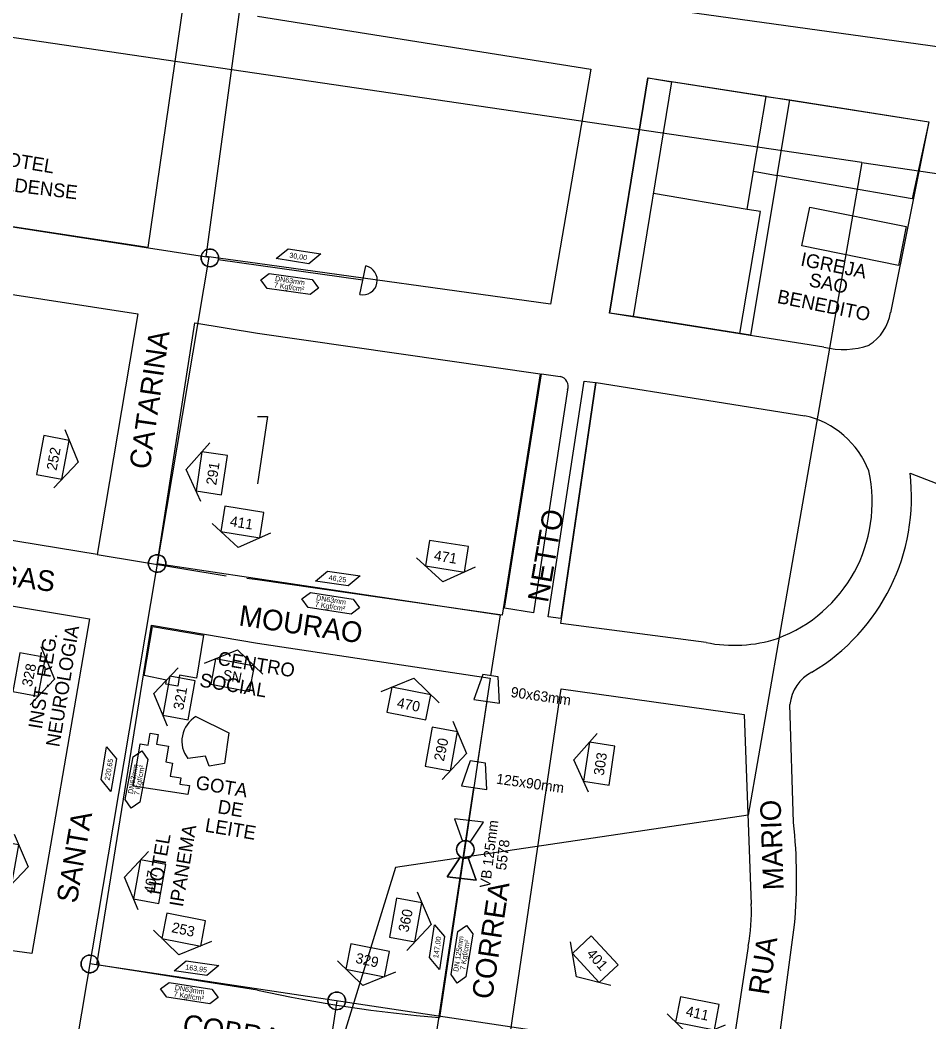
# Model space of a CAD drawing. Extents: x 325709 to 364434, y 7573432 to 7597073.
# Drawn here: x 338412.3 to 338676.7, y 7589659.1 to 7589950.5 of the extents above; entities that cross this region are included whole.
import ezdxf

# ---------------------------------------------------------------- set-up
doc = ezdxf.new("R2010")
doc.units = 0
for name, color, linetype in [('EDIFEXISTENT', 7, 'Continuous'), ('EDIFIDENTIF', 7, 'Continuous'), ('EDIFOBRAEXIS', 7, 'Continuous'), ('FORMATO', 7, 'Continuous'), ('LIMITE_BAIRROS_MUNICIPIOS', 7, 'Continuous'), ('LOGRADOURO', 7, 'Continuous'), ('LOGRADOURO_TEXTO', 7, 'Continuous'), ('NUM_REF', 7, 'Continuous'), ('SIMBOLO', 7, 'Continuous'), ('TEXTO', 7, 'Continuous'), ('TUBO_PEAD_GN_125', 7, 'Continuous'), ('TUBO_PEAD_GN_63', 7, 'Continuous'), ('TUBO_PEAD_GN_90', 7, 'Continuous'), ('VALVULA_PEAD_125', 7, 'Continuous')]:
    doc.layers.add(name, color=color, linetype=linetype)

# ---------------------------------------------------------------- blocks, each defined once
blk = doc.blocks.new('INTERLIGACAO')
at = {"layer": 'SIMBOLO'}
blk.add_circle((0, 0), 1.28, dxfattribs=at)
for start, end in [(0, 180), (180, 0)]:
    blk.add_arc((0, 0), 1.28, start, end, dxfattribs=at)
blk = doc.blocks.new('VALVULA_PEAD_DN_125')
at = {"layer": 'VALVULA_PEAD_125'}
for points in [[(-1.14, 0.57), (-4.25, 2.13), (-4.25, -2.13), (-1.14, -0.57)], [(-1.14, -0.57), (-4.25, -2.13), (-4.25, 2.13), (-1.14, 0.57)], [(1.14, -0.57), (4.25, -2.13), (4.25, 2.13), (1.14, 0.57)], [(1.14, -0.57), (4.25, -2.13), (4.25, 2.13), (1.14, 0.57)]]:
    blk.add_lwpolyline(points, dxfattribs=at)
blk.add_circle((0, 0), 1.28, dxfattribs=at)
for start, end in [(90, 270), (153.4349, 206.5651), (270, 90), (0, 26.5651), (333.4349, 0)]:
    blk.add_arc((0, 0), 1.28, start, end, dxfattribs=at)
blk = doc.blocks.new('NUM_REF')
at = {"layer": 'NUM_REF'}
blk.add_lwpolyline([(-4.3125, 0.9375), (0, 3.75), (4.3125, 0.9375)], dxfattribs=at)
blk.add_lwpolyline([(2.875, -1.875), (2.875, 1.875), (-2.875, 1.875), (-2.875, -1.875)], close=True, dxfattribs=at)

msp = doc.modelspace()

# ---------------------------------------------------------------- linework, layer by layer
at = {"layer": 'EDIFEXISTENT'}
for p, q in [((338639.76, 7589884.83), (338642.03, 7589896.12)), ((338642.03, 7589896.12), (338670.08, 7589890.5)), ((338670.08, 7589890.5), (338667.8, 7589879.14)), ((338667.8, 7589879.14), (338639.76, 7589884.83)), ((338448.43, 7589759.9), (338450.8, 7589774.11)), ((338450.8, 7589774.11), (338465.71, 7589771.65)), ((338465.71, 7589771.65), (338463.62, 7589759.14)), ((338454.92, 7589758.53), (338448.43, 7589759.9)), ((338454.73, 7589757.35), (338454.92, 7589758.53)), ((338458.72, 7589759.95), (338458.19, 7589756.77)), ((338463.62, 7589759.14), (338458.72, 7589759.95)), ((338458.19, 7589756.77), (338454.73, 7589757.35)), ((338463.45, 7589747.92), (338473.02, 7589743.23)), ((338449.53, 7589739.59), (338450.12, 7589743.11)), ((338450.12, 7589743.11), (338452.5, 7589742.71)), ((338473.02, 7589743.23), (338471.76, 7589734.27)), ((338452.5, 7589742.71), (338452.02, 7589739.86)), ((338445.21, 7589727.73), (338447.24, 7589739.97)), ((338447.24, 7589739.97), (338449.53, 7589739.59)), ((338452.02, 7589739.86), (338455.45, 7589739.28)), ((338455.45, 7589739.28), (338454.69, 7589734.73)), ((338454.69, 7589734.73), (338456.63, 7589734.4)), ((338456.63, 7589734.4), (338456, 7589730.59)), ((338466.26, 7589736.44), (338461.1, 7589735.74)), ((338467.36, 7589733.47), (338466.26, 7589736.44)), ((338471.76, 7589734.27), (338467.36, 7589733.47)), ((338456, 7589730.59), (338459.11, 7589730.07)), ((338459.11, 7589730.07), (338458.81, 7589728.31)), ((338461.12, 7589725.27), (338445.21, 7589727.73)), ((338458.81, 7589728.31), (338461.55, 7589727.85)), ((338461.55, 7589727.85), (338461.12, 7589725.27))]:
    msp.add_line(p, q, dxfattribs=at)
msp.add_arc((338467.66, 7589740.79), 8.28, 120.5749, 217.6076, dxfattribs=at)
at = {"layer": 'EDIFOBRAEXIS'}
for p, q in [((338629.36, 7589928.3), (338601.76, 7589932.58)), ((338623.84, 7589895.45), (338596.59, 7589900.03)), ((338553.2, 7589779.46), (338563.95, 7589847.61)), ((338563.95, 7589847.61), (338569.45, 7589846.88))]:
    msp.add_line(p, q, dxfattribs=at)
for points in [[(338595.05, 7589933.71), (338601.76, 7589932.58), (338590.63, 7589864.25), (338583.85, 7589865.24), (338595.05, 7589933.71)], [(338632.55, 7589905.28), (338636.26, 7589927.32), (338676.66, 7589920.95), (338671.85, 7589898.5), (338632.55, 7589905.28), (338624.74, 7589858.83), (338590.63, 7589864.25)], [(338625.7, 7589906.53), (338629.36, 7589928.3), (338636.26, 7589927.32)], [(338621.68, 7589859.31), (338627.65, 7589894.8), (338623.84, 7589895.45), (338625.7, 7589906.53), (338632.55, 7589905.28)], [(338576.43, 7589845.49), (338579.7, 7589845.06), (338569.6, 7589776.44), (338565.96, 7589776.96), (338576.43, 7589845.49)], [(338571.58, 7589842.92), (338561.71, 7589778.11), (338553.2, 7589779.46)], [(338481.39, 7589835.2), (338484.25, 7589835.24), (338481.39, 7589815.66)]]:
    msp.add_lwpolyline(points, dxfattribs=at)
msp.add_arc((338568.75, 7589843.95), 3.01, 340.1239, 76.6385, dxfattribs=at)
at = {"layer": 'LIMITE_BAIRROS_MUNICIPIOS'}
for points in [[(338657.19, 7589909.08), (338356.45, 7589953.26), (338434.11, 7590441.43), (338663.22, 7590410.21), (338845.4, 7590916.1), (338997.9, 7590425.8), (339063.34, 7590450), (338912.59, 7589871.56)], [(338657.19, 7589909.08), (338624.06, 7589719.21), (338521.53, 7589704.01), (338334.9, 7589099.85)], [(338657.19, 7589909.08), (338912.59, 7589871.56), (338870.82, 7589718.61), (338775.61, 7589646.81), (338916.66, 7589627.18)]]:
    msp.add_lwpolyline(points, dxfattribs=at)
at = {"layer": 'LOGRADOURO'}
for p, q in [((338459.81, 7589955.81), (338449.46, 7589884.34)), ((338702.07, 7589939.52), (338599.37, 7589953.79)), ((338466.44, 7589881.7), (338476.15, 7589952.8)), ((338481.39, 7589951.68), (338578.31, 7589936.19)), ((338578.31, 7589936.19), (338566.58, 7589867.92)), ((338583.75, 7589865.24), (338594.94, 7589933.71)), ((338594.94, 7589933.71), (338676.66, 7589920.95)), ((338676.66, 7589920.95), (338665.53, 7589865.4)), ((338449.46, 7589884.34), (338347.7, 7589899.92)), ((338344.5, 7589880.7), (338446.57, 7589865.1)), ((338481.39, 7589879.69), (338466.44, 7589881.7)), ((338566.58, 7589867.92), (338481.39, 7589879.69)), ((338446.57, 7589865.1), (338434.76, 7589795.04)), ((338646.16, 7589855.4), (338583.75, 7589865.24)), ((338452.15, 7589792.12), (338463.14, 7589862.44)), ((338463.14, 7589862.44), (338481.39, 7589859.4)), ((338481.39, 7589859.4), (338563.59, 7589847.61)), ((338563.59, 7589847.61), (338552.52, 7589777.4)), ((338569.59, 7589775.02), (338579.88, 7589845.11)), ((338579.88, 7589845.11), (338640.62, 7589835.42)), ((338671.22, 7589818.75), (338679.02, 7589815.75)), ((338434.76, 7589795.04), (338332.86, 7589811.81)), ((338330.98, 7589793.1), (338432.47, 7589776.35)), ((338472.25, 7589788.79), (338434.77, 7589795)), ((338481.39, 7589787.68), (338478.26, 7589788.06)), ((338552.52, 7589777.4), (338481.39, 7589787.68)), ((338432.47, 7589776.35), (338415.76, 7589678.98)), ((338434.61, 7589675.68), (338450.52, 7589774.49)), ((338450.52, 7589774.49), (338481.39, 7589769.31)), ((338611.85, 7589769.48), (338569.59, 7589775.02)), ((338481.39, 7589769.31), (338549.08, 7589759.07)), ((338549.08, 7589759.07), (338534.31, 7589660.36)), ((338555.1, 7589656.84), (338569.67, 7589755.95)), ((338569.67, 7589755.95), (338622.97, 7589748.52)), ((338637.32, 7589717.1), (338636.25, 7589751.42)), ((338622.97, 7589748.52), (338625.01, 7589693.41)), ((338415.76, 7589678.98), (338368.65, 7589685.54)), ((338632.15, 7589646.32), (338637.59, 7589687.34)), ((338624.08, 7589681.1), (338619.44, 7589650.41)), ((338481.39, 7589668.37), (338434.61, 7589675.68))]:
    msp.add_line(p, q, dxfattribs=at)
for centre, radius, start, end in [((338651.76, 7589867.74), 13.96, 302.7485, 350.3695), ((338651.76, 7589877.02), 22.34, 255.4876, 289.7614), ((338634.73, 7589809.83), 26.26, 21.2953, 77.0253), ((338617.95, 7589810.26), 42.23, 290.2865, 12.4538), ((338612.3, 7589811.81), 59.32, 300.7532, 6.7095), ((338620, 7589809.52), 40.87, 258.4936, 287.9446), ((338648, 7589750.32), 11.8, 116.9963, 174.6442), ((338487.33, 7589700.86), 150.87, 354.8597, 6.1799), ((338572.07, 7589691.21), 52.99, 349.0101, 2.3865), ((338569.82, 7590074.08), 415.24, 257.7038, 265.0934)]:
    msp.add_arc(centre, radius, start, end, dxfattribs=at)
at = {"layer": 'SIMBOLO'}
for points in [[(338496.31, 7589879.62), (338486.82, 7589881.11), (338490.3, 7589883.98), (338499.8, 7589882.49)], [(338484.8, 7589876.8), (338497.3, 7589875.03), (338499.16, 7589872.56), (338499.16, 7589872.56), (338496.69, 7589870.7), (338484.19, 7589872.46), (338482.33, 7589874.94), (338482.33, 7589874.94)], [(338507.78, 7589785.95), (338498.26, 7589787.3), (338501.71, 7589790.22), (338511.22, 7589788.87)], [(338496.78, 7589783.98), (338509.25, 7589782.05), (338511.08, 7589779.55), (338511.08, 7589779.55), (338508.58, 7589777.72), (338496.11, 7589779.66), (338494.28, 7589782.16), (338494.28, 7589782.16)], [(338551.78, 7589751.86), (338551.35, 7589759.5), (338546.89, 7589760.13), (338544.35, 7589752.92)], [(338440.32, 7589735.59), (338438.71, 7589726.12), (338435.89, 7589729.64), (338437.49, 7589739.11)], [(338442.86, 7589723.83), (338445.17, 7589736.25), (338447.72, 7589738), (338447.72, 7589738), (338449.47, 7589735.45), (338447.16, 7589723.03), (338444.61, 7589721.28), (338444.61, 7589721.28)], [(338548.11, 7589726.75), (338547.67, 7589734.38), (338543.22, 7589735.01), (338540.68, 7589727.8)], [(338535.74, 7589683.92), (338534.36, 7589674.41), (338531.45, 7589677.86), (338532.83, 7589687.37)], [(338537.68, 7589672.92), (338539.65, 7589685.39), (338542.15, 7589687.21), (338542.15, 7589687.21), (338543.97, 7589684.71), (338542, 7589672.24), (338539.5, 7589670.42), (338539.5, 7589670.42)], [(338466.66, 7589672.58), (338457.15, 7589673.93), (338460.59, 7589676.85), (338470.11, 7589675.5)], [(338455.66, 7589670.61), (338468.14, 7589668.67), (338469.96, 7589666.18), (338469.96, 7589666.18), (338467.47, 7589664.35), (338454.99, 7589666.28), (338453.17, 7589668.78), (338453.17, 7589668.78)]]:
    msp.add_lwpolyline(points, close=True, dxfattribs=at)
at = {"layer": 'TUBO_PEAD_GN_125'}
msp.add_line((338544.24, 7589727.3), (338517.75, 7589553.63), dxfattribs=at)
at = {"layer": 'TUBO_PEAD_GN_63'}
for p, q in [((338342.16, 7589900.77), (338467.18, 7589881.59)), ((338467.18, 7589881.59), (338421.99, 7589612.77)), ((338511.97, 7589874.82), (338469.96, 7589880.81)), ((338512.84, 7589878.98), (338511.09, 7589870.65)), ((338452.19, 7589792.4), (338551.92, 7589777.49)), ((338551.93, 7589777.5), (338549.12, 7589759.82)), ((338631.24, 7589646.28), (338432.62, 7589675.98)), ((338504.43, 7589665.24), (338499.9, 7589635.59))]:
    msp.add_line(p, q, dxfattribs=at)
msp.add_arc((338511.97, 7589874.82), 4.25, 258.156, 78.156, dxfattribs=at)
at = {"layer": 'TUBO_PEAD_GN_90'}
msp.add_line((338548.07, 7589752.39), (338545.37, 7589734.71), dxfattribs=at)

# ---------------------------------------------------------------- block references
at = {"layer": 'FORMATO'}
for p, xscale, yscale, rotation in [((338421.86, 7589823.31), 1.9999999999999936, 1.9999999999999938, -100.70632208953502), ((338468.06, 7589818.7), 1.9999999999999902, 1.9999999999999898, 81.3795703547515), ((338476.98, 7589804.53), 1.9999999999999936, 1.999999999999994, 170.91654670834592), ((338536.48, 7589794.55), 1.9999999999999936, 1.999999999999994, 170.91654670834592), ((338414.95, 7589760.17), 1.9999999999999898, 1.9999999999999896, -100.3090999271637), ((338474.12, 7589759.98), 1.9999999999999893, 1.9999999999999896, -10.741198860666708), ((338458.57, 7589753.32), 1.9999999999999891, 1.9999999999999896, 79.77047945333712), ((338525.41, 7589751.73), 1.9999999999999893, 1.9999999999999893, -11.202265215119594), ((338534.82, 7589738.49), 1.9999999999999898, 1.9999999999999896, -100.3090999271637), ((338580.78, 7589734.22), 1.9999999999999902, 1.9999999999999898, 81.3795703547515), ((338407.24, 7589705.59), 1.9999999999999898, 1.9999999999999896, -100.3090999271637), ((338450.03, 7589699.9), 1.9999999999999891, 1.9999999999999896, 79.77047945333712), ((338524.47, 7589688.76), 1.9999999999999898, 1.9999999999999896, -100.3090999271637), ((338459.92, 7589685.98), 1.9999999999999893, 1.9999999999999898, 168.96254512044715), ((338579.64, 7589677.35), 1.9999999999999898, 1.9999999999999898, 132.7983526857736), ((338513.43, 7589677.06), 1.9999999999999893, 1.9999999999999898, 168.96254512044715), ((338609.34, 7589661.64), 1.9999999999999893, 1.9999999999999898, 168.96254512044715)]:
    msp.add_blockref('NUM_REF', p, dxfattribs=dict(at, xscale=xscale, yscale=yscale, rotation=rotation))
at = {"layer": 'SIMBOLO'}
for p, xscale, yscale, rotation in [((338467.52, 7589881.33), 2, 2, -8.011999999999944), ((338452.18, 7589792.44), 2.0000000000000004, 1.9999999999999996, 22.031790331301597), ((338432.62, 7589675.98), 2.0000000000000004, 1.9999999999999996, 22.031790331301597), ((338504.43, 7589665.24), 2.0000000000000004, 1.9999999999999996, 22.031790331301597)]:
    msp.add_blockref('INTERLIGACAO', p, dxfattribs=dict(at, xscale=xscale, yscale=yscale, rotation=rotation))
at = {"layer": 'VALVULA_PEAD_125', "xscale": 1.9999999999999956, "yscale": 1.9999999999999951, "rotation": 82.88228201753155}
msp.add_blockref('VALVULA_PEAD_DN_125', (338541.84, 7589709.27), dxfattribs=at)

# ---------------------------------------------------------------- texts
for s, rotation, p in [('252', 79.2937, (338422.9, 7589819.35)), ('291', 81.3796, (338469.36, 7589815.08)), ('411', 350.9165, (338473.21, 7589803.35)), ('471', 350.9165, (338532.55, 7589793.4)), ('328', 78.2244, (338415.71, 7589756.44)), ('SN', 349.2588, (338471.04, 7589758.7)), ('321', 79.7705, (338459.78, 7589749.67)), ('470', 348.7977, (338521.75, 7589750.58)), ('290', 78.2244, (338535.58, 7589734.76)), ('303', 81.3796, (338582.08, 7589730.61)), ('VB 125mm', 82.8823, (338548.99, 7589697.93)), ('5578', 82.8823, (338553.66, 7589703.1)), ('407', 79.7705, (338451.23, 7589696.25)), ('360', 78.2244, (338525.22, 7589685.03)), ('253', 347.496, (338456.19, 7589685.27)), ('329', 347.496, (338509.69, 7589676.35)), ('401', 311.3318, (338576.88, 7589678.8)), ('411', 347.496, (338605.76, 7589660.9))]:
    msp.add_text(s, height=3, rotation=rotation).set_placement(p)
at = {"layer": 'EDIFIDENTIF'}
for s, rotation, p in [('HOTEL', 350.6301, (338404.32, 7589908.78)), ('CALDENSE', 353.1046, (338400.16, 7589901.81)), ('IGREJA', 348.67, (338639.14, 7589879.1)), ('SAO', 348.67, (338641.57, 7589873.11)), ('BENEDITO', 348.67, (338632.33, 7589868.26)), ('NEUROLOGIA', 80.6301, (338423.73, 7589738.89)), ('INST. REG.', 80.6301, (338418.62, 7589744.11)), ('CENTRO', 350.5534, (338469.58, 7589763.02)), ('SOCIAL', 350.5534, (338464.34, 7589756.69)), ('GOTA', 350.5534, (338463.19, 7589726.88)), ('DE', 350.5534, (338469.57, 7589719.85)), ('LEITE', 350.5534, (338465.91, 7589714.49)), ('IPANEMA', 80.5534, (338459.65, 7589692.38)), ('HOTEL', 80.5534, (338453.19, 7589695.93))]:
    msp.add_text(s, height=4, rotation=rotation, dxfattribs=at).set_placement(p)
at = {"layer": 'LOGRADOURO_TEXTO'}
for s, rotation, p in [('CATARINA', 81.7587, (338449.99, 7589819.61)), ('NETTO', 80.252, (338565.84, 7589780.86)), ('CHAGAS', 352.5268, (338388.5, 7589788.56)), ('MOURAO', 351.6288, (338475.71, 7589774.46)), ('MARIO', 92.0755, (338634.48, 7589697.55)), ('SANTA', 80.2658, (338428.79, 7589693.4)), ('CORREA', 81.4859, (338549.61, 7589665.46)), ('RUA', 81.3947, (338630.09, 7589666.72)), ('COBRA', 351.2235, (338459.3, 7589655.5))]:
    msp.add_text(s, height=6, rotation=rotation, dxfattribs=at).set_placement(p)
at = {"layer": 'TEXTO'}
for s, height, rotation, p in [('30,00', 1.5, 351.0538, (338490.56, 7589881.42)), ('7 Kgf/cm²', 1.5, 351.9655, (338486.08, 7589872.74)), ('DN63mm', 1.5, 351.9655, (338486.4, 7589874.61)), ('46,25', 1.5, 351.9239, (338502, 7589787.66)), ('7 Kgf/cm²', 1.5, 351.1832, (338498, 7589779.91)), ('DN63mm', 1.5, 351.1832, (338498.35, 7589781.78)), ('90x63mm', 3, 351.9158, (338554.9, 7589753.64)), ('220,65', 1.5, 80.3876, (338438.36, 7589729.29)), ('DN63mm', 1.5, 79.4593, (338445.11, 7589725.34)), ('7 Kgf/cm²', 1.5, 79.4593, (338446.97, 7589724.93)), ('125x90mm', 3, 351.9158, (338550.68, 7589728.44)), ('147,00', 1.5, 81.774, (338533.93, 7589677.58)), ('DN 125mm', 1.5, 81.0334, (338539.75, 7589673.62)), ('7 Kgf/cm²', 1.5, 81.0334, (338541.76, 7589674.13)), ('163,95', 1.5, 351.9239, (338460.31, 7589674.37)), ('7 Kgf/cm²', 1.5, 351.1832, (338456.88, 7589666.54)), ('DN63mm', 1.5, 351.1832, (338457.23, 7589668.4))]:
    msp.add_text(s, height=height, rotation=rotation, dxfattribs=at).set_placement(p)

doc.saveas('drawing.dxf')
